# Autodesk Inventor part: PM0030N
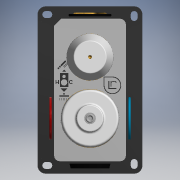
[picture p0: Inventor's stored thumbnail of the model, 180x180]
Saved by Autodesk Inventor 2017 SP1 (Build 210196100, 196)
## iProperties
Created: 2021-08
Part Number: PM0030N
Material: Generico
Document SubType Name: Modeling
Designer: ROSSETTO
Density: 1 g/cm^3
Appearance: Default
Author: ROSSETTO
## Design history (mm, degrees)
feature "Base2"
node "Solido1"
node "Solido3"
